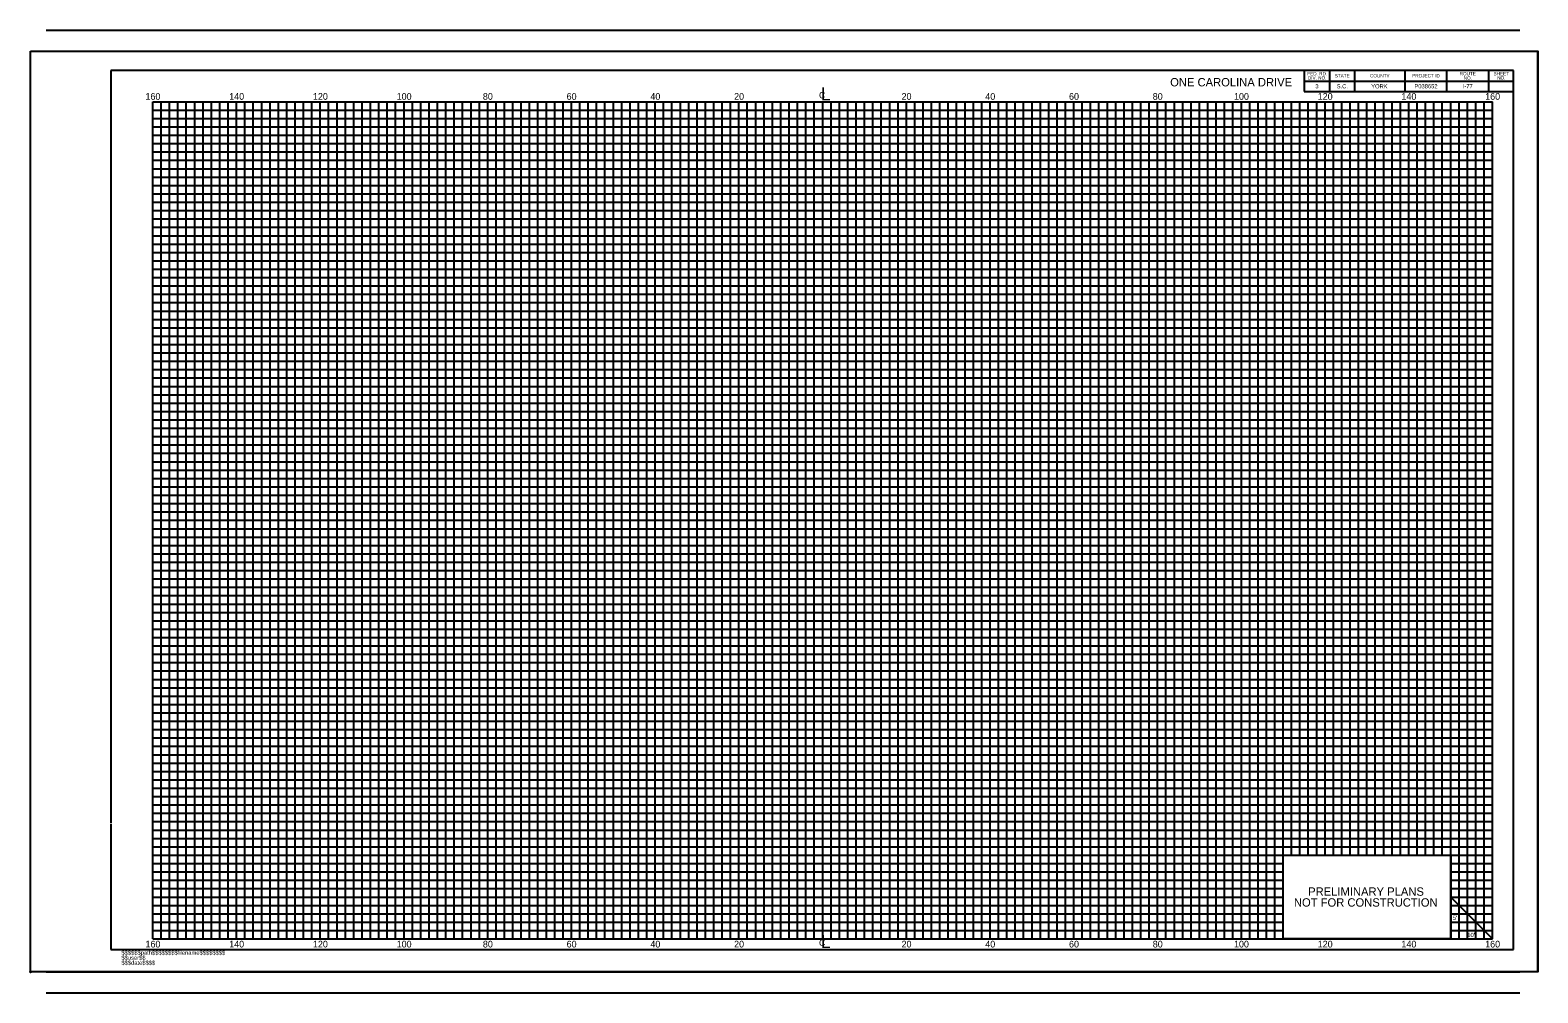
# Model space of a CAD drawing. Extents: x -15 to 165, y -6 to 109.
import ezdxf

# ---------------------------------------------------------------- set-up
doc = ezdxf.new("R2010")
doc.units = 0
for name, color, linetype in [('RD_DDB_StaTX', 7, 'Continuous'), ('RD_SHT_Bndy', 7, 'Continuous'), ('RD_SHT_ID', 7, 'Continuous'), ('RD_SHT_IplotShp', 7, 'Continuous'), ('RD_SHT_MjGrid_XS', 7, 'Continuous'), ('RD_SHT_MnGrid_XS', 7, 'Continuous'), ('RD_SHT_Snap', 7, 'Continuous'), ('RD_SHT_TX', 7, 'Continuous')]:
    doc.layers.add(name, color=color, linetype=linetype)

msp = doc.modelspace()

# ---------------------------------------------------------------- linework, layer by layer
at = {"layer": 'RD_SHT_Bndy'}
for p, q in [((-12.73, 108.55), (163.27, 108.55)), ((-12.73, 106.05), (163.27, 106.05)), ((-5, 103.72), (-5, 13.81)), ((162.51, 103.72), (-5, 103.72)), ((137.51, 103.72), (137.51, 101.22)), ((140.51, 103.72), (140.51, 101.22)), ((143.51, 103.72), (143.51, 101.22)), ((149.51, 103.72), (149.51, 101.22)), ((154.51, 103.72), (154.51, 101.22)), ((159.51, 103.72), (159.51, 101.22)), ((162.51, -1.28), (162.51, 103.72)), ((137.51, 102.47), (162.51, 102.47)), ((137.51, 101.22), (162.51, 101.22)), ((-5, 13.72), (-5, -1.28)), ((139.95, 5), (139.95, 5)), ((145, 5), (145, 5)), ((-5, -1.28), (162.51, -1.28)), ((-12.73, -3.95), (163.27, -3.95)), ((-12.73, -6.45), (163.27, -6.45))]:
    msp.add_line(p, q, dxfattribs=at)
msp.add_lwpolyline([(135, 10), (155, 10), (155, 0), (135, 0)], close=True, dxfattribs=at)
at = {"layer": 'RD_SHT_IplotShp'}
msp.add_lwpolyline([(-14.59, 106.05), (165.41, 106.05), (165.41, -3.95), (-14.59, -3.95)], close=True, dxfattribs=at)
at = {"layer": 'RD_SHT_MjGrid_XS'}
for p, q in [((0, 100), (160, 100)), ((0, 0), (0, 100)), ((5, 0), (5, 100)), ((10, 0), (10, 100)), ((15, 0), (15, 100)), ((20, 0), (20, 100)), ((25, 0), (25, 100)), ((30, 0), (30, 100)), ((35, 0), (35, 100)), ((40, 0), (40, 100)), ((45, 0), (45, 100)), ((50, 0), (50, 100)), ((55, 0), (55, 100)), ((60, 0), (60, 100)), ((65, 0), (65, 100)), ((70, 0), (70, 100)), ((75, 0), (75, 100)), ((80, 0), (80, 100)), ((85, 0), (85, 100)), ((90, 0), (90, 100)), ((95, 0), (95, 100)), ((100, 0), (100, 100)), ((105, 0), (105, 100)), ((110, 0), (110, 100)), ((115, 0), (115, 100)), ((120, 0), (120, 100)), ((125, 0), (125, 100)), ((130, 0), (130, 100)), ((135, 0), (135, 100)), ((140, 10), (140, 100)), ((145, 10), (145, 100)), ((150, 10), (150, 100)), ((155, 0), (155, 100)), ((160, 0), (160, 100)), ((0, 95), (160, 95)), ((0, 90), (160, 90)), ((0, 85), (160, 85)), ((0, 80), (160, 80)), ((0, 75), (160, 75)), ((0, 70), (160, 70)), ((0, 65), (160, 65)), ((0, 60), (160, 60)), ((0, 55), (160, 55)), ((0, 50), (160, 50)), ((0, 45), (160, 45)), ((0, 40), (160, 40)), ((0, 35), (160, 35)), ((0, 30), (160, 30)), ((0, 25), (160, 25)), ((0, 20), (160, 20)), ((0, 15), (160, 15)), ((0, 10), (160, 10)), ((0, 5), (135, 5)), ((155, 5), (160, 0)), ((155, 5), (160, 5)), ((0, 0), (160, 0))]:
    msp.add_line(p, q, dxfattribs=at)
at = {"layer": 'RD_SHT_MnGrid_XS'}
for p, q in [((1, 0), (1, 100)), ((2, 0), (2, 100)), ((3, 0), (3, 100)), ((4, 0), (4, 100)), ((6, 0), (6, 100)), ((7, 0), (7, 100)), ((8, 0), (8, 100)), ((9, 0), (9, 100)), ((11, 0), (11, 100)), ((12, 0), (12, 100)), ((13, 0), (13, 100)), ((14, 0), (14, 100)), ((16, 0), (16, 100)), ((17, 0), (17, 100)), ((18, 0), (18, 100)), ((19, 0), (19, 100)), ((21, 0), (21, 100)), ((22, 0), (22, 100)), ((23, 0), (23, 100)), ((24, 0), (24, 100)), ((26, 0), (26, 100)), ((27, 0), (27, 100)), ((28, 0), (28, 100)), ((29, 0), (29, 100)), ((31, 0), (31, 100)), ((32, 0), (32, 100)), ((33, 0), (33, 100)), ((34, 0), (34, 100)), ((36, 0), (36, 100)), ((37, 0), (37, 100)), ((38, 0), (38, 100)), ((39, 0), (39, 100)), ((41, 0), (41, 100)), ((42, 0), (42, 100)), ((43, 0), (43, 100)), ((44, 0), (44, 100)), ((46, 0), (46, 100)), ((47, 0), (47, 100)), ((48, 0), (48, 100)), ((49, 0), (49, 100)), ((51, 0), (51, 100)), ((52, 0), (52, 100)), ((53, 0), (53, 100)), ((54, 0), (54, 100)), ((56, 0), (56, 100)), ((57, 0), (57, 100)), ((58, 0), (58, 100)), ((59, 0), (59, 100)), ((61, 0), (61, 100)), ((62, 0), (62, 100)), ((63, 0), (63, 100)), ((64, 0), (64, 100)), ((66, 0), (66, 100)), ((67, 0), (67, 100)), ((68, 0), (68, 100)), ((69, 0), (69, 100)), ((71, 0), (71, 100)), ((72, 0), (72, 100)), ((73, 0), (73, 100)), ((74, 0), (74, 100)), ((76, 0), (76, 100)), ((77, 0), (77, 100)), ((78, 0), (78, 100)), ((79, 0), (79, 100)), ((81, 0), (81, 100)), ((82, 0), (82, 100)), ((83, 0), (83, 100)), ((84, 0), (84, 100)), ((86, 0), (86, 100)), ((87, 0), (87, 100)), ((88, 0), (88, 100)), ((89, 0), (89, 100)), ((91, 0), (91, 100)), ((92, 0), (92, 100)), ((93, 0), (93, 100)), ((94, 0), (94, 100)), ((96, 0), (96, 100)), ((97, 0), (97, 100)), ((98, 0), (98, 100)), ((99, 0), (99, 100)), ((101, 0), (101, 100)), ((102, 0), (102, 100)), ((103, 0), (103, 100)), ((104, 0), (104, 100)), ((106, 0), (106, 100)), ((107, 0), (107, 100)), ((108, 0), (108, 100)), ((109, 0), (109, 100)), ((111, 0), (111, 100)), ((112, 0), (112, 100)), ((113, 0), (113, 100)), ((114, 0), (114, 100)), ((116, 0), (116, 100)), ((117, 0), (117, 100)), ((118, 0), (118, 100)), ((119, 0), (119, 100)), ((121, 0), (121, 100)), ((122, 0), (122, 100)), ((123, 0), (123, 100)), ((124, 0), (124, 100)), ((126, 0), (126, 100)), ((127, 0), (127, 100)), ((128, 0), (128, 100)), ((129, 0), (129, 100)), ((131, 0), (131, 100)), ((132, 0), (132, 100)), ((133, 0), (133, 100)), ((134, 0), (134, 100)), ((136, 10), (136, 100)), ((137, 10), (137, 100)), ((138, 10), (138, 100)), ((139, 10), (139, 100)), ((141, 10), (141, 100)), ((142, 10), (142, 100)), ((143, 10), (143, 100)), ((144, 10), (144, 100)), ((146, 10), (146, 100)), ((147, 10), (147, 100)), ((148, 10), (148, 100)), ((149, 10), (149, 100)), ((151, 10), (151, 100)), ((152, 10), (152, 100)), ((153, 10), (153, 100)), ((154, 10), (154, 100)), ((156, 0), (156, 100)), ((157, 0), (157, 100)), ((158, 0), (158, 100)), ((159, 0), (159, 100)), ((0, 99), (160, 99)), ((0, 98), (160, 98)), ((0, 97), (160, 97)), ((0, 96), (160, 96)), ((0, 94), (160, 94)), ((0, 93), (160, 93)), ((0, 92), (160, 92)), ((0, 91), (160, 91)), ((0, 89), (160, 89)), ((0, 88), (160, 88)), ((0, 87), (160, 87)), ((0, 86), (160, 86)), ((0, 84), (160, 84)), ((0, 83), (160, 83)), ((0, 82), (160, 82)), ((0, 81), (160, 81)), ((0, 79), (160, 79)), ((0, 78), (160, 78)), ((0, 77), (160, 77)), ((0, 76), (160, 76)), ((0, 74), (160, 74)), ((0, 73), (160, 73)), ((0, 72), (160, 72)), ((0, 71), (160, 71)), ((0, 69), (160, 69)), ((0, 68), (160, 68)), ((0, 67), (160, 67)), ((0, 66), (160, 66)), ((0, 64), (160, 64)), ((0, 63), (160, 63)), ((0, 62), (160, 62)), ((0, 61), (160, 61)), ((0, 59), (160, 59)), ((0, 58), (160, 58)), ((0, 57), (160, 57)), ((0, 56), (160, 56)), ((0, 54), (160, 54)), ((0, 53), (160, 53)), ((0, 52), (160, 52)), ((0, 51), (160, 51)), ((0, 49), (160, 49)), ((0, 48), (160, 48)), ((0, 47), (160, 47)), ((0, 46), (160, 46)), ((0, 44), (160, 44)), ((0, 43), (160, 43)), ((0, 42), (160, 42)), ((0, 41), (160, 41)), ((0, 39), (160, 39)), ((0, 38), (160, 38)), ((0, 37), (160, 37)), ((0, 36), (160, 36)), ((0, 34), (160, 34)), ((0, 33), (160, 33)), ((0, 32), (160, 32)), ((0, 31), (160, 31)), ((0, 29), (160, 29)), ((0, 28), (160, 28)), ((0, 27), (160, 27)), ((0, 26), (160, 26)), ((0, 24), (160, 24)), ((0, 23), (160, 23)), ((0, 22), (160, 22)), ((0, 21), (160, 21)), ((0, 21), (160, 21)), ((0, 19), (160, 19)), ((0, 18), (160, 18)), ((0, 17), (160, 17)), ((0, 16), (160, 16)), ((0, 14), (160, 14)), ((0, 13), (160, 13)), ((0, 12), (160, 12)), ((0, 11), (160, 11)), ((0, 9), (135, 9)), ((0, 8), (135, 8)), ((155, 9), (160, 9)), ((155, 8), (160, 8)), ((0, 7), (135, 7)), ((0, 6), (135, 6)), ((155, 7), (160, 7)), ((155, 6), (160, 6)), ((0, 4), (135, 4)), ((155, 4), (160, 4)), ((0, 3), (135, 3)), ((0, 2), (135, 2)), ((155, 3), (160, 3)), ((155, 2), (160, 2)), ((0, 1), (135, 1)), ((155, 1), (160, 1))]:
    msp.add_line(p, q, dxfattribs=at)
at = {"layer": 'RD_SHT_Snap'}
for p, q in [((-14.59, -3.95), (-14.59, 106.05)), ((165.41, -3.95), (165.41, 106.05))]:
    msp.add_line(p, q, dxfattribs=at)
msp.add_circle((-14.59, -3.95), 0.0607, dxfattribs=at)

# ---------------------------------------------------------------- texts
at = {"layer": 'RD_DDB_StaTX'}
for s, height, p in [('160', 0.8, (-0.88, 100.23)), ('140', 0.8, (9.12, 100.23)), ('120', 0.8, (19.12, 100.23)), ('100', 0.8, (29.12, 100.23)), ('80', 0.8, (39.42, 100.23)), ('60', 0.8, (49.42, 100.23)), ('40', 0.8, (59.42, 100.23)), ('20', 0.8, (69.42, 100.23)), ('C', 0.773, (79.56, 100.4)), ('L', 1.55, (79.79, 100.16)), ('20', 0.8, (89.42, 100.23)), ('40', 0.8, (99.42, 100.23)), ('60', 0.8, (109.42, 100.23)), ('80', 0.8, (119.42, 100.23)), ('100', 0.8, (129.12, 100.23)), ('120', 0.8, (139.12, 100.23)), ('140', 0.8, (149.12, 100.23)), ('160', 0.8, (159.12, 100.23)), ('L', 1.55, (79.79, -1.09)), ('160', 0.8, (-0.88, -1.03)), ('140', 0.8, (9.12, -1.03)), ('120', 0.8, (19.12, -1.03)), ('100', 0.8, (29.12, -1.03)), ('80', 0.8, (39.42, -1.03)), ('60', 0.8, (49.42, -1.03)), ('40', 0.8, (59.42, -1.03)), ('20', 0.8, (69.42, -1.03)), ('C', 0.773, (79.56, -0.85)), ('20', 0.8, (89.42, -1.03)), ('40', 0.8, (99.42, -1.03)), ('60', 0.8, (109.42, -1.03)), ('80', 0.8, (119.42, -1.03)), ('100', 0.8, (129.12, -1.03)), ('120', 0.8, (139.12, -1.03)), ('140', 0.8, (149.12, -1.03)), ('160', 0.8, (159.12, -1.03))]:
    msp.add_text(s, height=height, dxfattribs=at).set_placement(p)
at = {"layer": 'RD_SHT_ID'}
for s, p in [('$$$$$$path$$$$$$$$filename$$$$$$$$', (-3.75, -1.9)), ('$$user$$', (-3.75, -2.5)), ('$$$date$$$$', (-3.75, -3.1))]:
    msp.add_text(s, height=0.5, rotation=360, dxfattribs=at).set_placement(p)
at = {"layer": 'RD_SHT_TX'}
for s, height, p in [('ONE CAROLINA DRIVE', 1, (121.5, 101.83)), ('FED. RD.', 0.4, (137.88, 103.15)), ('DIV. NO.', 0.4, (137.95, 102.65)), ('STATE', 0.4, (141.15, 102.9)), ('COUNTY', 0.4, (145.37, 102.9)), ('PROJECT ID', 0.4, (150.41, 102.9)), ('ROUTE', 0.4, (156.07, 103.15)), ('NO.', 0.4, (156.56, 102.63)), ('SHEET', 0.4, (160.12, 103.15)), ('NO.', 0.4, (160.56, 102.65)), ('3', 0.5, (138.84, 101.6)), ('S.C.', 0.5, (141.39, 101.6)), ('YORK', 0.5, (145.51, 101.6)), ('P038652', 0.5, (150.67, 101.6)), ('I-77', 0.5, (156.44, 101.6)), ('PRELIMINARY PLANS', 1, (137.98, 5.15)), ('NOT FOR CONSTRUCTION', 1, (136.28, 3.85)), ("5'", 0.512, (155.26, 2.26)), ("10'", 0.512, (156.97, 0.21))]:
    msp.add_text(s, height=height, dxfattribs=at).set_placement(p)

doc.saveas('drawing.dxf')
